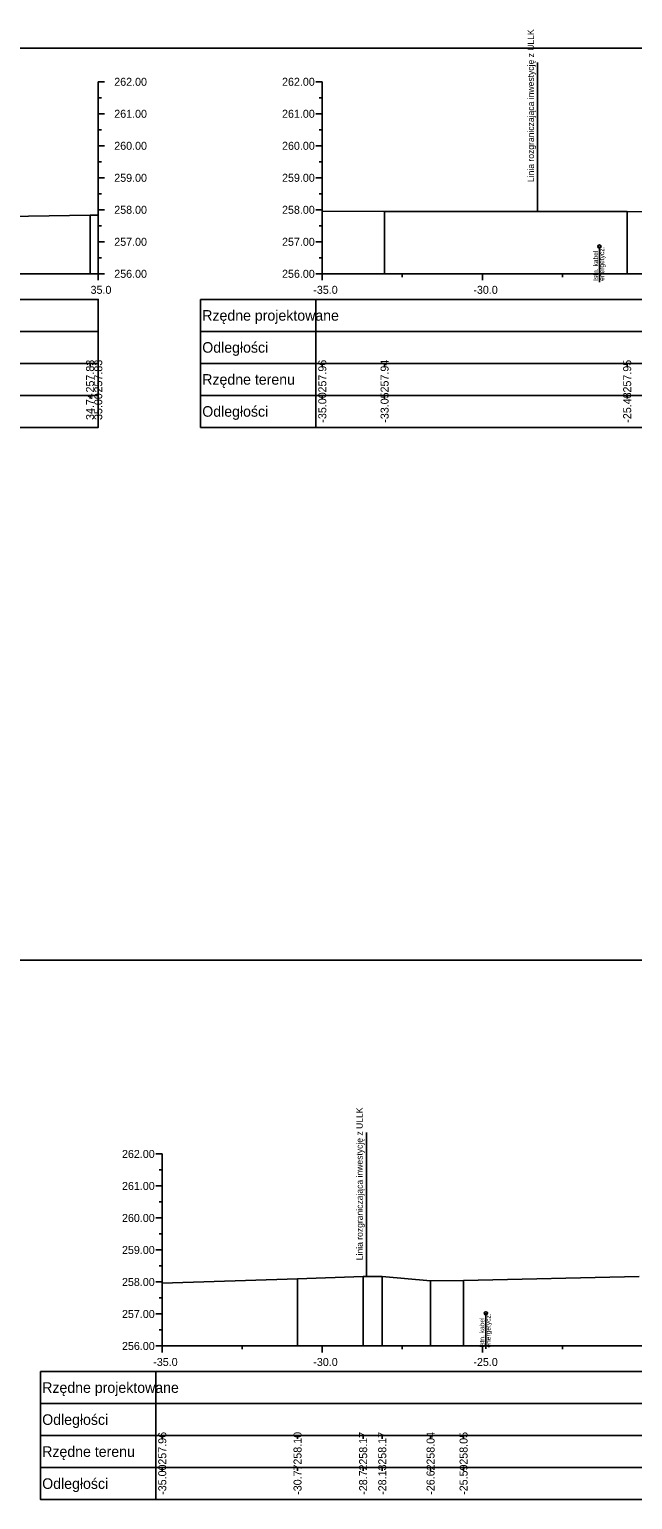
# Model space of a CAD drawing. Extents: x 6516023 to 6560129, y 5513077 to 5529206.
# Drawn here: x 6516518.31 to 6516537.16, y 5514501.31 to 5514547.24 of the extents above; entities that cross this region are included whole.
import ezdxf

# ---------------------------------------------------------------- set-up
doc = ezdxf.new("R2010")
doc.units = 0
for name, color, linetype in [('TOR_PRZEK_P-kable', 7, 'Continuous'), ('TOR_PRZEK_P-tabelka istniejace', 7, 'Continuous'), ('TOR_PRZEK_P-tabelka projektowane', 7, 'Continuous'), ('TOR_PRZEK_P-teren istniejacy', 7, 'Continuous'), ('TOR_PRZEK_P-uklad odniesienia', 7, 'Continuous'), ('TOR_PS_T-granica PKP-projektowana', 7, 'Continuous'), ('TOR_RAMKI-ramka+tabelka 1', 7, 'Continuous')]:
    doc.layers.add(name, color=color, linetype=linetype)

msp = doc.modelspace()

# ---------------------------------------------------------------- linework, layer by layer
at = {"layer": 'TOR_PRZEK_P-kable'}
for p, q in [((6516536.121, 5514540.459), (6516536.121, 5514539.349)), ((6516532.573, 5514507.128), (6516532.573, 5514506.018))]:
    msp.add_line(p, q, dxfattribs=at)
for centre in [(6516536.121, 5514540.459), (6516532.573, 5514507.128)]:
    msp.add_circle(centre, 0.05, dxfattribs=at)
at = {"layer": 'TOR_PRZEK_P-tabelka istniejace'}
for p, q in [((6516520.207, 5514536.706), (6516520.207, 5514536.806)), ((6516520.463, 5514536.706), (6516520.463, 5514536.806)), ((6516523.663, 5514536.806), (6516523.663, 5514534.806)), ((6516527.263, 5514536.806), (6516527.263, 5514534.806)), ((6516527.463, 5514536.706), (6516527.463, 5514536.806)), ((6516529.409, 5514536.706), (6516529.409, 5514536.806)), ((6516536.987, 5514536.706), (6516536.987, 5514536.806)), ((6516446.663, 5514535.806), (6516520.463, 5514535.806)), ((6516520.207, 5514535.706), (6516520.207, 5514535.806)), ((6516520.463, 5514535.706), (6516520.463, 5514535.806)), ((6516523.663, 5514535.806), (6516597.463, 5514535.806)), ((6516527.463, 5514535.706), (6516527.463, 5514535.806)), ((6516529.409, 5514535.706), (6516529.409, 5514535.806)), ((6516536.987, 5514535.706), (6516536.987, 5514535.806)), ((6516518.663, 5514503.306), (6516518.663, 5514501.306)), ((6516522.263, 5514503.306), (6516522.263, 5514501.306)), ((6516522.463, 5514503.206), (6516522.463, 5514503.306)), ((6516526.689, 5514503.206), (6516526.689, 5514503.306)), ((6516528.739, 5514503.206), (6516528.739, 5514503.306)), ((6516529.335, 5514503.206), (6516529.335, 5514503.306)), ((6516530.845, 5514503.206), (6516530.845, 5514503.306)), ((6516531.876, 5514503.206), (6516531.876, 5514503.306)), ((6516518.663, 5514502.306), (6516592.463, 5514502.306)), ((6516522.463, 5514502.206), (6516522.463, 5514502.306)), ((6516526.689, 5514502.206), (6516526.689, 5514502.306)), ((6516528.739, 5514502.206), (6516528.739, 5514502.306)), ((6516529.335, 5514502.206), (6516529.335, 5514502.306)), ((6516530.845, 5514502.206), (6516530.845, 5514502.306)), ((6516531.876, 5514502.206), (6516531.876, 5514502.306))]:
    msp.add_line(p, q, dxfattribs=at)
for points in [[(6516527.463, 5514541.568), (6516527.463, 5514539.806), (6516527.463, 5514539.676), (6516527.463, 5514539.606)], [(6516529.409, 5514541.549), (6516529.409, 5514539.806), (6516529.409, 5514539.676), (6516529.409, 5514539.606)], [(6516536.987, 5514541.555), (6516536.987, 5514539.806), (6516536.987, 5514539.676), (6516536.987, 5514539.606)], [(6516520.207, 5514541.437), (6516520.207, 5514539.806), (6516520.207, 5514539.676), (6516520.207, 5514539.606)], [(6516520.463, 5514541.439), (6516520.463, 5514539.806), (6516520.463, 5514539.676), (6516520.463, 5514539.606)], [(6516522.463, 5514508.067), (6516522.463, 5514506.306), (6516522.463, 5514506.176), (6516522.463, 5514506.106)], [(6516526.689, 5514508.208), (6516526.689, 5514506.306), (6516526.689, 5514506.176), (6516526.689, 5514506.106)], [(6516528.739, 5514508.272), (6516528.739, 5514506.306), (6516528.739, 5514506.176), (6516528.739, 5514506.106)], [(6516529.335, 5514508.278), (6516529.335, 5514506.306), (6516529.335, 5514506.176), (6516529.335, 5514506.106)], [(6516530.845, 5514508.143), (6516530.845, 5514506.306), (6516530.845, 5514506.176), (6516530.845, 5514506.106)], [(6516531.876, 5514508.152), (6516531.876, 5514506.306), (6516531.876, 5514506.176), (6516531.876, 5514506.106)]]:
    msp.add_lwpolyline(points, dxfattribs=at)
for points in [[(6516446.663, 5514536.806), (6516446.663, 5514534.806), (6516520.463, 5514534.806), (6516520.463, 5514536.806)], [(6516523.663, 5514536.806), (6516523.663, 5514534.806), (6516597.463, 5514534.806), (6516597.463, 5514536.806)], [(6516518.663, 5514503.306), (6516518.663, 5514501.306), (6516592.463, 5514501.306), (6516592.463, 5514503.306)]]:
    msp.add_lwpolyline(points, close=True, dxfattribs=at)
at = {"layer": 'TOR_PRZEK_P-tabelka projektowane'}
for p, q in [((6516523.663, 5514538.806), (6516523.663, 5514536.806)), ((6516527.263, 5514538.806), (6516527.263, 5514536.806)), ((6516446.663, 5514537.806), (6516520.463, 5514537.806)), ((6516523.663, 5514537.806), (6516597.463, 5514537.806)), ((6516518.663, 5514505.306), (6516518.663, 5514503.306)), ((6516522.263, 5514505.306), (6516522.263, 5514503.306)), ((6516518.663, 5514504.306), (6516592.463, 5514504.306))]:
    msp.add_line(p, q, dxfattribs=at)
for points in [[(6516446.663, 5514538.806), (6516446.663, 5514536.806), (6516520.463, 5514536.806), (6516520.463, 5514538.806)], [(6516523.663, 5514538.806), (6516523.663, 5514536.806), (6516597.463, 5514536.806), (6516597.463, 5514538.806)], [(6516518.663, 5514505.306), (6516518.663, 5514503.306), (6516592.463, 5514503.306), (6516592.463, 5514505.306)]]:
    msp.add_lwpolyline(points, close=True, dxfattribs=at)
at = {"layer": 'TOR_PRZEK_P-teren istniejacy'}
for points in [[(6516527.463, 5514541.568), (6516529.409, 5514541.549), (6516536.987, 5514541.555), (6516539.477, 5514541.5)], [(6516514.421, 5514541.345), (6516520.207, 5514541.437), (6516520.463, 5514541.439)], [(6516522.463, 5514508.067), (6516526.689, 5514508.208), (6516528.739, 5514508.272), (6516529.335, 5514508.278), (6516530.845, 5514508.143), (6516531.876, 5514508.152), (6516537.357, 5514508.272)]]:
    msp.add_lwpolyline(points, dxfattribs=at)
at = {"layer": 'TOR_PRZEK_P-uklad odniesienia'}
for p, q in [((6516520.463, 5514545.606), (6516520.463, 5514539.606)), ((6516520.663, 5514545.606), (6516520.463, 5514545.606)), ((6516527.263, 5514545.606), (6516527.463, 5514545.606)), ((6516527.463, 5514545.606), (6516527.463, 5514539.606)), ((6516520.563, 5514545.106), (6516520.463, 5514545.106)), ((6516527.363, 5514545.106), (6516527.463, 5514545.106)), ((6516520.663, 5514544.606), (6516520.463, 5514544.606)), ((6516527.263, 5514544.606), (6516527.463, 5514544.606)), ((6516520.563, 5514544.106), (6516520.463, 5514544.106)), ((6516527.363, 5514544.106), (6516527.463, 5514544.106)), ((6516520.663, 5514543.606), (6516520.463, 5514543.606)), ((6516527.263, 5514543.606), (6516527.463, 5514543.606)), ((6516520.563, 5514543.106), (6516520.463, 5514543.106)), ((6516527.363, 5514543.106), (6516527.463, 5514543.106)), ((6516520.663, 5514542.606), (6516520.463, 5514542.606)), ((6516527.263, 5514542.606), (6516527.463, 5514542.606)), ((6516520.563, 5514542.106), (6516520.463, 5514542.106)), ((6516527.363, 5514542.106), (6516527.463, 5514542.106)), ((6516520.663, 5514541.606), (6516520.463, 5514541.606)), ((6516527.263, 5514541.606), (6516527.463, 5514541.606)), ((6516520.563, 5514541.106), (6516520.463, 5514541.106)), ((6516527.363, 5514541.106), (6516527.463, 5514541.106)), ((6516520.663, 5514540.606), (6516520.463, 5514540.606)), ((6516527.263, 5514540.606), (6516527.463, 5514540.606)), ((6516520.563, 5514540.106), (6516520.463, 5514540.106)), ((6516527.363, 5514540.106), (6516527.463, 5514540.106)), ((6516450.463, 5514539.606), (6516520.463, 5514539.606)), ((6516520.463, 5514539.406), (6516520.463, 5514539.606)), ((6516520.663, 5514539.606), (6516520.463, 5514539.606)), ((6516527.263, 5514539.606), (6516527.463, 5514539.606)), ((6516527.463, 5514539.606), (6516597.463, 5514539.606)), ((6516527.463, 5514539.406), (6516527.463, 5514539.606)), ((6516529.963, 5514539.506), (6516529.963, 5514539.606)), ((6516532.463, 5514539.406), (6516532.463, 5514539.606)), ((6516534.963, 5514539.506), (6516534.963, 5514539.606)), ((6516522.263, 5514512.106), (6516522.463, 5514512.106)), ((6516522.463, 5514512.106), (6516522.463, 5514506.106)), ((6516522.363, 5514511.606), (6516522.463, 5514511.606)), ((6516522.263, 5514511.106), (6516522.463, 5514511.106)), ((6516522.363, 5514510.606), (6516522.463, 5514510.606)), ((6516522.263, 5514510.106), (6516522.463, 5514510.106)), ((6516522.363, 5514509.606), (6516522.463, 5514509.606)), ((6516522.263, 5514509.106), (6516522.463, 5514509.106)), ((6516522.363, 5514508.606), (6516522.463, 5514508.606)), ((6516522.263, 5514508.106), (6516522.463, 5514508.106)), ((6516522.363, 5514507.606), (6516522.463, 5514507.606)), ((6516522.263, 5514507.106), (6516522.463, 5514507.106)), ((6516522.363, 5514506.606), (6516522.463, 5514506.606)), ((6516522.263, 5514506.106), (6516522.463, 5514506.106)), ((6516522.463, 5514506.106), (6516592.463, 5514506.106)), ((6516522.463, 5514506.006), (6516522.463, 5514506.106)), ((6516522.463, 5514505.906), (6516522.463, 5514506.106)), ((6516524.963, 5514506.006), (6516524.963, 5514506.106)), ((6516527.463, 5514505.906), (6516527.463, 5514506.106)), ((6516529.963, 5514506.006), (6516529.963, 5514506.106)), ((6516532.463, 5514505.906), (6516532.463, 5514506.106)), ((6516534.963, 5514506.006), (6516534.963, 5514506.106))]:
    msp.add_line(p, q, dxfattribs=at)
at = {"layer": 'TOR_PS_T-granica PKP-projektowana'}
for p, q in [((6516534.188, 5514541.552), (6516534.188, 5514546.21)), ((6516528.839, 5514508.273), (6516528.839, 5514512.775))]:
    msp.add_line(p, q, dxfattribs=at)
at = {"layer": 'TOR_RAMKI-ramka+tabelka 1'}
msp.add_lwpolyline([(6516362.013, 5514546.656), (6516609.513, 5514546.656), (6516609.513, 5514518.156), (6516362.013, 5514518.156)], close=True, dxfattribs=at)

# ---------------------------------------------------------------- texts
at = {"layer": 'TOR_PRZEK_P-kable'}
for s, p in [('Istn. kabel', (6516536.076, 5514539.386)), ('energetycz.', (6516536.27, 5514539.386)), ('energetycz.', (6516532.722, 5514506.055)), ('Istn. kabel', (6516532.528, 5514506.054))]:
    msp.add_text(s, height=0.14999, rotation=90.0511, dxfattribs=at).set_placement(p)
at = {"layer": 'TOR_PRZEK_P-tabelka istniejace'}
for s, p in [('257.83', (6516520.332, 5514535.898)), ('257.83', (6516520.588, 5514535.898)), ('257.96', (6516527.588, 5514535.898)), ('257.94', (6516529.534, 5514535.899)), ('257.95', (6516537.112, 5514535.897)), ('34.74', (6516520.332, 5514535.039)), ('35.00', (6516520.588, 5514535.038)), ('-35.00', (6516527.588, 5514534.955)), ('-33.05', (6516529.534, 5514534.953)), ('-25.48', (6516537.112, 5514534.954)), ('257.96', (6516522.588, 5514502.398)), ('258.10', (6516526.814, 5514502.398)), ('258.17', (6516528.864, 5514502.398)), ('258.17', (6516529.46, 5514502.398)), ('258.04', (6516530.97, 5514502.399)), ('258.05', (6516532.001, 5514502.397)), ('-35.00', (6516522.588, 5514501.455)), ('-30.77', (6516526.814, 5514501.455)), ('-28.72', (6516528.864, 5514501.456)), ('-28.13', (6516529.46, 5514501.454)), ('-26.62', (6516530.97, 5514501.456)), ('-25.59', (6516532.001, 5514501.455))]:
    msp.add_text(s, height=0.25, rotation=90, dxfattribs=at).set_placement(p)
for s, p in [('Rzędne terenu', (6516523.713, 5514536.141)), ('Odległości', (6516523.713, 5514535.141)), ('Rzędne terenu', (6516518.713, 5514502.641)), ('Odległości', (6516518.713, 5514501.641))]:
    msp.add_text(s, height=0.33, dxfattribs=at).set_placement(p)
at = {"layer": 'TOR_PRZEK_P-tabelka projektowane'}
for s, p in [('Rzędne projektowane', (6516523.713, 5514538.141)), ('Odległości', (6516523.713, 5514537.141)), ('Rzędne projektowane', (6516518.713, 5514504.641)), ('Odległości', (6516518.713, 5514503.641))]:
    msp.add_text(s, height=0.33, dxfattribs=at).set_placement(p)
at = {"layer": 'TOR_PRZEK_P-uklad odniesienia'}
for s, height, p in [('262.00', 0.25, (6516520.963, 5514545.481)), ('262.00', 0.25, (6516526.205, 5514545.481)), ('261.00', 0.25, (6516520.963, 5514544.481)), ('261.00', 0.25, (6516526.205, 5514544.481)), ('260.00', 0.25, (6516520.963, 5514543.481)), ('260.00', 0.25, (6516526.205, 5514543.481)), ('259.00', 0.25, (6516520.963, 5514542.481)), ('259.00', 0.25, (6516526.205, 5514542.481)), ('258.00', 0.25, (6516520.963, 5514541.481)), ('258.00', 0.25, (6516526.205, 5514541.481)), ('257.00', 0.25, (6516520.963, 5514540.481)), ('257.00', 0.25, (6516526.205, 5514540.481)), ('256.00', 0.25, (6516520.963, 5514539.481)), ('256.00', 0.25, (6516526.205, 5514539.481)), ('35.0', 0.25, (6516520.224, 5514538.981)), ('-35.0', 0.25, (6516527.182, 5514538.981)), ('-', 0.0001, (6516527.463, 5514539.606)), ('-30.0', 0.25, (6516532.182, 5514538.981)), ('262.00', 0.25, (6516521.205, 5514511.981)), ('261.00', 0.25, (6516521.205, 5514510.981)), ('260.00', 0.25, (6516521.205, 5514509.981)), ('259.00', 0.25, (6516521.205, 5514508.981)), ('258.00', 0.25, (6516521.205, 5514507.981)), ('257.00', 0.25, (6516521.205, 5514506.981)), ('256.00', 0.25, (6516521.205, 5514505.981)), ('-35.0', 0.25, (6516522.182, 5514505.481)), ('-', 0.0001, (6516522.463, 5514506.106)), ('-30.0', 0.25, (6516527.182, 5514505.481)), ('-25.0', 0.25, (6516532.182, 5514505.481))]:
    msp.add_text(s, height=height, dxfattribs=at).set_placement(p)
at = {"layer": 'TOR_PS_T-granica PKP-projektowana'}
for p in [(6516534.078, 5514542.474), (6516528.729, 5514508.785)]:
    msp.add_text('Linia rozgraniczająca inwestycję z ULLK', height=0.2, rotation=90.0511, dxfattribs=at).set_placement(p)

doc.saveas('drawing.dxf')
